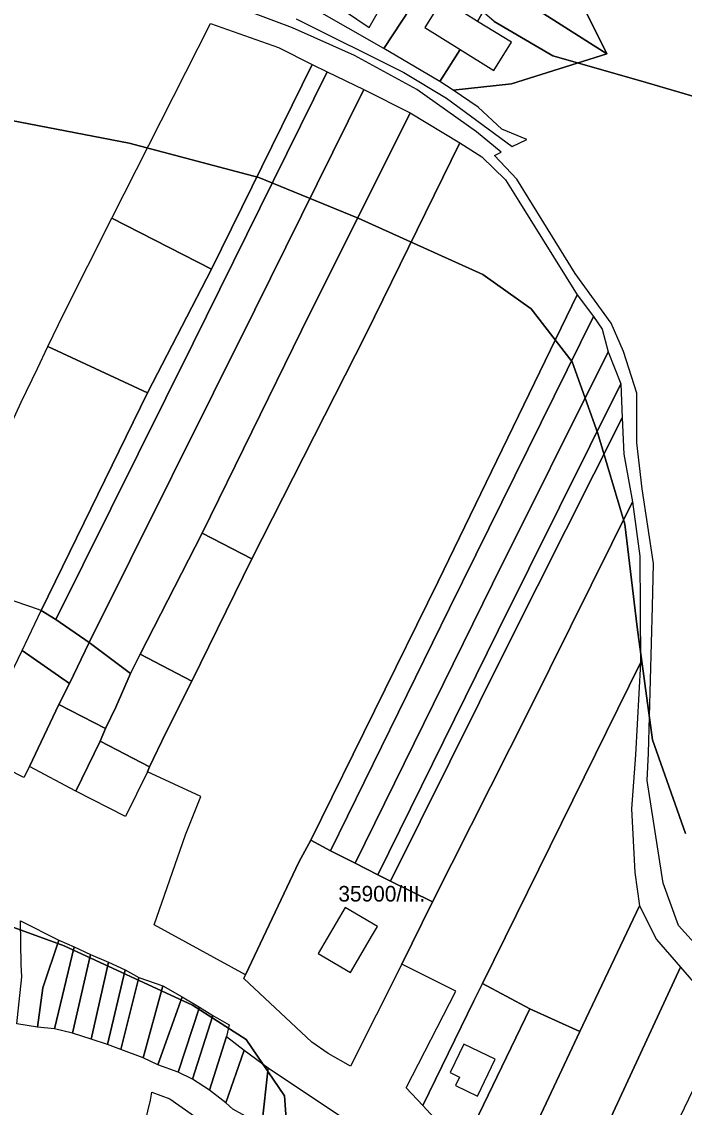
# Model space of a CAD drawing. Extents: x -532083 to -529270, y -1180561 to -1176456.
# Drawn here: x -530420.1 to -530207.8, y -1178347.7 to -1178000.1 of the extents above; entities that cross this region are included whole.
import ezdxf

# ---------------------------------------------------------------- set-up
doc = ezdxf.new("R2010")
doc.units = 0
for name, color, linetype in [('95560013', 7, 'Continuous'), ('95590013', 7, 'Continuous'), ('95660013', 7, 'Continuous')]:
    doc.layers.add(name, color=color, linetype=linetype)

msp = doc.modelspace()

# ---------------------------------------------------------------- linework, layer by layer
at = {"layer": '95560013'}
for points in [[(-530299.8523, -1177901.09045), (-530280.6013, -1177914.22245), (-530232.5793, -1178010.35345), (-530267.4413, -1177988.16645), (-530284.2703, -1177978.51945), (-530305.4283, -1177965.25545), (-530335.0003, -1177946.44445), (-530349.6663, -1177937.28045), (-530363.9053, -1177927.50045), (-530378.2703, -1177918.86645), (-530380.2003, -1177917.50445), (-530355.5573, -1177879.63945), (-530348.2853, -1177868.05345)], [(-530359.2473, -1178079.28545), (-530391.1673, -1178062.95745), (-530359.6163, -1178000.68345), (-530337.7763, -1178008.31145), (-530327.0513, -1178013.78845)], [(-530413.8453, -1178188.63145), (-530379.7523, -1178118.93845), (-530359.2473, -1178079.28545), (-530327.0513, -1178013.78845), (-530322.1763, -1178016.13545), (-530365.1503, -1178103.06945), (-530409.1523, -1178191.48945)], [(-530398.4243, -1178198.88845), (-530409.1523, -1178191.48945), (-530365.1503, -1178103.06945), (-530322.1763, -1178016.13545), (-530310.4773, -1178021.80745), (-530345.3953, -1178092.32145)], [(-530385.1813, -1178208.80845), (-530398.4243, -1178198.88845), (-530345.3953, -1178092.32145), (-530310.4773, -1178021.80745), (-530295.6573, -1178029.24045), (-530330.4543, -1178098.92645), (-530362.2753, -1178163.84345), (-530382.1233, -1178202.62845)], [(-530346.3653, -1178172.03845), (-530362.2753, -1178163.84345), (-530330.4543, -1178098.92645), (-530295.6573, -1178029.24045), (-530279.6673, -1178038.82445), (-530309.7773, -1178100.23945)], [(-530379.7523, -1178118.93845), (-530411.6723, -1178104.09445), (-530406.5993, -1178093.49245), (-530391.1673, -1178062.95745), (-530359.2473, -1178079.28545)], [(-530321.1613, -1178265.59045), (-530327.4363, -1178262.14345), (-530286.6053, -1178179.34845), (-530242.0943, -1178087.56745), (-530236.8883, -1178094.45145), (-530283.0603, -1178187.88145)], [(-530313.2433, -1178269.48745), (-530321.1613, -1178265.59045), (-530283.0603, -1178187.88145), (-530236.8883, -1178094.45145), (-530234.0483, -1178098.48645), (-530232.1553, -1178105.84445), (-530269.2383, -1178180.05945)], [(-530413.8453, -1178188.63145), (-530417.1983, -1178187.45445), (-530447.2033, -1178177.36645), (-530439.1443, -1178159.98045), (-530431.5973, -1178145.03745), (-530426.0363, -1178134.47845), (-530420.2763, -1178121.92745), (-530414.9933, -1178111.09845), (-530411.6723, -1178104.09445), (-530379.7523, -1178118.93845)], [(-530305.9223, -1178273.23345), (-530313.2433, -1178269.48745), (-530269.2383, -1178180.05945), (-530232.1553, -1178105.84445), (-530228.1323, -1178116.05145), (-530267.4663, -1178194.99145)], [(-530305.9223, -1178273.23345), (-530267.4663, -1178194.99145), (-530228.1323, -1178116.05145), (-530227.6593, -1178126.97045), (-530263.9213, -1178198.90245), (-530301.8883, -1178275.33145)], [(-530288.4423, -1178281.92545), (-530301.8883, -1178275.33145), (-530263.9213, -1178198.90245), (-530227.6593, -1178126.97045), (-530227.1863, -1178138.60145), (-530224.3463, -1178153.79245), (-530257.5423, -1178220.58845)], [(-530281.0333, -1178310.56745), (-530298.2973, -1178301.90845), (-530288.4423, -1178281.92545), (-530257.5423, -1178220.58845), (-530224.3463, -1178153.79245), (-530221.9943, -1178171.23945), (-530221.8493, -1178205.35845), (-530272.3883, -1178308.05445), (-530275.2123, -1178313.58745), (-530291.5473, -1178347.09445), (-530296.8833, -1178341.48745)], [(-530365.5663, -1178211.24845), (-530382.1233, -1178202.62845), (-530362.2753, -1178163.84345), (-530346.3653, -1178172.03845)], [(-530404.7943, -1178212.00345), (-530419.8803, -1178201.41045), (-530413.8453, -1178188.63145), (-530409.1523, -1178191.48945), (-530398.4243, -1178198.88845)], [(-530393.2273, -1178226.46345), (-530408.1463, -1178218.72845), (-530404.7943, -1178212.00345), (-530398.4243, -1178198.88845), (-530385.1813, -1178208.80845), (-530389.8753, -1178219.56945)], [(-530379.1473, -1178238.73745), (-530394.9043, -1178230.49845), (-530393.2273, -1178226.46345), (-530389.8753, -1178219.56945), (-530385.1813, -1178208.80845), (-530382.1233, -1178202.62845), (-530365.5663, -1178211.24845), (-530373.9493, -1178227.85545)], [(-530241.2393, -1178323.39945), (-530257.2783, -1178316.15445), (-530272.3883, -1178308.05445), (-530221.8493, -1178205.35845), (-530223.4123, -1178234.88645), (-530224.7153, -1178252.13345), (-530223.6733, -1178272.51545), (-530222.1003, -1178283.20345)], [(-530402.7823, -1178246.47145), (-530417.5333, -1178238.56945), (-530408.1463, -1178218.72845), (-530393.2273, -1178226.46345), (-530394.9043, -1178230.49845)], [(-530386.8583, -1178254.54245), (-530402.7823, -1178246.47145), (-530394.9043, -1178230.49845), (-530379.1473, -1178238.73745), (-530379.8173, -1178240.25045)], [(-530327.1373, -1178326.88445), (-530348.9503, -1178306.50345), (-530348.3553, -1178305.24545), (-530331.3213, -1178269.18745), (-530327.4363, -1178262.14345), (-530321.1613, -1178265.59045), (-530313.2433, -1178269.48745), (-530305.9223, -1178273.23345), (-530301.8883, -1178275.33145), (-530288.4423, -1178281.92545), (-530298.2973, -1178301.90845), (-530314.7583, -1178334.52945), (-530321.9083, -1178330.48145)], [(-530268.9313, -1178404.44445), (-530271.9803, -1178388.89645), (-530241.2393, -1178323.39945), (-530222.1003, -1178283.20345), (-530216.7173, -1178294.00245), (-530209.0493, -1178302.79245), (-530259.4933, -1178411.81445), (-530260.8003, -1178411.07145)], [(-530314.7493, -1178304.58345), (-530307.6873, -1178292.54045), (-530306.0983, -1178289.83045), (-530316.4743, -1178283.74645), (-530325.1253, -1178298.49845)], [(-530243.0333, -1178421.17245), (-530259.4933, -1178411.81445), (-530209.0493, -1178302.79245), (-530206.2503, -1178306.00145), (-530194.2883, -1178319.80045)], [(-530279.6043, -1178362.38845), (-530285.4483, -1178353.72145), (-530291.5473, -1178347.09445), (-530275.2123, -1178313.58745), (-530272.3883, -1178308.05445), (-530257.2783, -1178316.15445)], [(-530274.2673, -1178373.60345), (-530279.6043, -1178362.38845), (-530257.2783, -1178316.15445), (-530241.2393, -1178323.39945), (-530271.9803, -1178388.89645)], [(-530359.9123, -1178342.27245), (-530365.3563, -1178338.74945), (-530358.8593, -1178318.31645), (-530353.5903, -1178321.31045), (-530354.4693, -1178325.00945)], [(-530274.0833, -1178344.14445), (-530268.3733, -1178332.34245), (-530278.3713, -1178327.50545), (-530282.7823, -1178336.62345), (-530279.7933, -1178338.06945), (-530281.0913, -1178340.75345)], [(-530369.3503, -1178364.54045), (-530379.6213, -1178362.08645), (-530380.9243, -1178367.53945), (-530383.8903, -1178366.83045), (-530382.8323, -1178362.15845), (-530378.8473, -1178345.40345), (-530378.3393, -1178342.84345), (-530372.5833, -1178345.03345), (-530361.8673, -1178352.59745), (-530365.8363, -1178363.94445), (-530369.7843, -1178381.12645), (-530370.7973, -1178386.43945), (-530376.3543, -1178385.04545), (-530381.3163, -1178384.05045), (-530386.8723, -1178382.85645), (-530385.4833, -1178376.28645), (-530384.7793, -1178370.55045), (-530381.4303, -1178371.35145), (-530381.6973, -1178372.46845), (-530371.8093, -1178374.83145)]]:
    msp.add_lwpolyline(points, close=True, dxfattribs=at)
for points in [[(-530332.1213, -1177999.11845), (-530297.6073, -1178016.33145), (-530283.9573, -1178024.54645), (-530262.8983, -1178039.99845), (-530258.2183, -1178037.84645), (-530266.2133, -1178034.52145), (-530273.8173, -1178027.48045), (-530281.8123, -1178022.00345), (-530263.1133, -1178020.00045), (-530232.5793, -1178010.35345), (-530280.6013, -1177914.22245)], [(-530187.4763, -1178314.06145), (-530209.6193, -1178289.54245), (-530214.5083, -1178275.98545), (-530219.6843, -1178243.10045), (-530219.2443, -1178234.36445), (-530217.9413, -1178187.32845), (-530217.6033, -1178173.53545), (-530221.2843, -1178149.67845), (-530222.9833, -1178134.91045), (-530222.9833, -1178119.00545), (-530227.2303, -1178105.65745), (-530231.1943, -1178096.56945), (-530242.8033, -1178080.66445), (-530261.4903, -1178050.55945), (-530268.5583, -1178042.91745), (-530266.4693, -1178041.86945), (-530274.4023, -1178035.30345), (-530293.5123, -1178021.80745), (-530313.4023, -1178010.85445), (-530333.2913, -1178002.05245), (-530356.6913, -1177993.25045)]]:
    msp.add_lwpolyline(points, dxfattribs=at)
at = {"layer": '95590013'}
for points in [[(-530304.0423, -1178008.70245), (-530326.8563, -1177995.59845), (-530323.9403, -1177991.54245), (-530308.7943, -1178001.91245), (-530304.0193, -1177993.75745), (-530297.6613, -1177983.05845), (-530307.3683, -1177977.28945), (-530311.1983, -1177974.90245), (-530305.4283, -1177965.25545), (-530284.2703, -1177978.51945)], [(-530285.3103, -1177992.98445), (-530290.8923, -1178001.98745), (-530279.6113, -1178008.98245), (-530286.1023, -1178019.26545), (-530304.0423, -1178008.70245), (-530284.2703, -1177978.51945), (-530267.4413, -1177988.16645), (-530274.0223, -1177999.96945), (-530278.3863, -1177997.26345), (-530277.3233, -1177995.55045), (-530280.8163, -1177993.38445), (-530281.8853, -1177995.10845)], [(-530263.1133, -1178020.00045), (-530281.8123, -1178022.00345), (-530286.1023, -1178019.26545), (-530279.6113, -1178008.98245), (-530268.7783, -1178015.70045), (-530263.1893, -1178006.68745), (-530274.0223, -1177999.96945), (-530267.4413, -1177988.16645), (-530232.5793, -1178010.35345)], [(-530362.6463, -1178248.24145), (-530379.8173, -1178240.25045), (-530379.1473, -1178238.73745), (-530373.9493, -1178227.85545), (-530365.5663, -1178211.24845), (-530346.3653, -1178172.03845), (-530309.7773, -1178100.23945), (-530279.6673, -1178038.82445), (-530272.6473, -1178043.32345), (-530265.0433, -1178050.75545), (-530260.7533, -1178057.60145), (-530242.0943, -1178087.56745), (-530286.6053, -1178179.34845), (-530327.4363, -1178262.14345), (-530331.3213, -1178269.18745), (-530348.3553, -1178305.24545), (-530377.6083, -1178289.27445), (-530367.6363, -1178260.51245)], [(-530419.3773, -1178242.10045), (-530435.6373, -1178233.86145), (-530419.8803, -1178201.41045), (-530404.7943, -1178212.00345), (-530408.1463, -1178218.72845), (-530417.5333, -1178238.56945)], [(-530420.0753, -1178305.90845), (-530420.2933, -1178302.00745), (-530420.5153, -1178287.96345), (-530408.2053, -1178294.18345), (-530413.2973, -1178309.50845), (-530415.0533, -1178322.01545), (-530421.6263, -1178320.95545), (-530421.1823, -1178316.94345)], [(-530415.0533, -1178322.01545), (-530413.2973, -1178309.50845), (-530408.2053, -1178294.18345), (-530403.2883, -1178296.29745), (-530409.6093, -1178322.54345)], [(-530403.8143, -1178323.95245), (-530409.6093, -1178322.54345), (-530403.2883, -1178296.29745), (-530398.0193, -1178298.76345)], [(-530397.8443, -1178325.89045), (-530403.8143, -1178323.95245), (-530398.0193, -1178298.76345), (-530392.2243, -1178301.22945)], [(-530397.8443, -1178325.89045), (-530392.2243, -1178301.22945), (-530386.9563, -1178303.69545), (-530392.5753, -1178327.65245)], [(-530392.5753, -1178327.65245), (-530386.9563, -1178303.69545), (-530382.5663, -1178306.16145), (-530388.3613, -1178329.23745)], [(-530388.3613, -1178329.23745), (-530382.5663, -1178306.16145), (-530374.8393, -1178308.80445), (-530381.1613, -1178331.87945)], [(-530381.1613, -1178331.87945), (-530374.8393, -1178308.80445), (-530368.6933, -1178312.32745), (-530376.4203, -1178334.16945)], [(-530369.9223, -1178336.45945), (-530376.4203, -1178334.16945), (-530368.6933, -1178312.32745), (-530363.0733, -1178315.67345)], [(-530369.9223, -1178336.45945), (-530363.0733, -1178315.67345), (-530358.8593, -1178318.31645), (-530365.3563, -1178338.74945)], [(-530359.9123, -1178342.27245), (-530365.3563, -1178338.74945), (-530358.8593, -1178318.31645), (-530353.5903, -1178321.31045), (-530354.4693, -1178325.00945)], [(-530359.9123, -1178342.27245), (-530354.4693, -1178325.00945), (-530348.8493, -1178329.41345), (-530354.6443, -1178346.32345)], [(-530343.1843, -1178353.47045), (-530352.4813, -1178348.32945), (-530354.6443, -1178346.32345), (-530348.8493, -1178329.41345), (-530341.1033, -1178335.09745)], [(-530310.2983, -1178378.52445), (-530329.6553, -1178359.52545), (-530343.1843, -1178353.47045), (-530341.1033, -1178335.09745), (-530315.7093, -1178352.00945), (-530299.4743, -1178357.43745), (-530298.0173, -1178359.94245), (-530288.0263, -1178380.40345), (-530284.6963, -1178394.39245), (-530285.9453, -1178402.53445), (-530286.9863, -1178406.29245), (-530300.0993, -1178389.17245)]]:
    msp.add_lwpolyline(points, close=True, dxfattribs=at)
at = {"layer": '95660013'}
for points in [[(-530201.3753, -1178025.00045), (-530221.8123, -1178019.00045), (-530249.8753, -1178011.00045), (-530268.6873, -1178000.00045), (-530273.3753, -1177996.00045), (-530290.8123, -1177984.00045), (-530320.3123, -1177971.00045), (-530358.3753, -1177957.00045), (-530382.3753, -1177953.00045), (-530405.8753, -1177951.00045), (-530439.3123, -1177953.00045), (-530481.5003, -1177966.00045), (-530485.6253, -1177969.00045), (-530485.3753, -1177967.00045), (-530487.6253, -1177940.00045), (-530452.8753, -1177905.00045), (-530429.1253, -1177888.00045), (-530404.6253, -1177878.00045), (-530371.3753, -1177872.00045), (-530342.3123, -1177868.00045), (-530305.8123, -1177867.00045), (-530259.0003, -1177872.00045), (-530208.6253, -1177869.00045), (-530150.3123, -1177866.00045)], [(-530207.3753, -1178260.00045), (-530218.0003, -1178230.00045), (-530222.8753, -1178194.00045), (-530226.8753, -1178161.00045), (-530235.5003, -1178132.00045), (-530243.6873, -1178109.00045), (-530256.8123, -1178092.00045), (-530272.3123, -1178081.00045), (-530312.3123, -1178063.00045), (-530344.1253, -1178050.00045), (-530385.6873, -1178039.00045), (-530432.3123, -1178030.00045), (-530462.0003, -1178026.00045), (-530492.1873, -1178015.00045), (-530502.0003, -1178012.00045), (-530495.5003, -1178004.00045), (-530489.3753, -1178000.00045)], [(-530268.6873, -1178000.00045), (-530249.8753, -1178011.00045), (-530221.8123, -1178019.00045), (-530201.3753, -1178025.00045)], [(-530432.3123, -1178030.00045), (-530385.6873, -1178039.00045), (-530344.1253, -1178050.00045), (-530312.3123, -1178063.00045), (-530272.3123, -1178081.00045), (-530256.8123, -1178092.00045), (-530243.6873, -1178109.00045), (-530235.5003, -1178132.00045), (-530226.8753, -1178161.00045), (-530222.8753, -1178194.00045), (-530218.0003, -1178230.00045), (-530207.3753, -1178260.00045)], [(-530427.8123, -1178351.00045), (-530452.3753, -1178343.00045), (-530512.5003, -1178327.00045), (-530534.3753, -1178320.00045), (-530533.8123, -1178299.00045), (-530537.1253, -1178275.00045), (-530542.0003, -1178254.00045), (-530537.8753, -1178253.00045), (-530526.5003, -1178255.00045), (-530496.3123, -1178264.00045), (-530489.6873, -1178266.00045), (-530458.8123, -1178277.00045), (-530406.5003, -1178296.00045), (-530365.3123, -1178315.00045), (-530348.1873, -1178326.00045), (-530335.8753, -1178344.00045), (-530334.3123, -1178366.00045)], [(-530334.3123, -1178366.00045), (-530335.8753, -1178344.00045), (-530348.1873, -1178326.00045), (-530365.3123, -1178315.00045), (-530406.5003, -1178296.00045), (-530458.8123, -1178277.00045)]]:
    msp.add_lwpolyline(points, dxfattribs=at)

# ---------------------------------------------------------------- texts
msp.add_text('35900/III.', height=5, rotation=0, dxfattribs=at).set_placement((-530318.62187, -1178281.83195))

doc.saveas('drawing.dxf')
